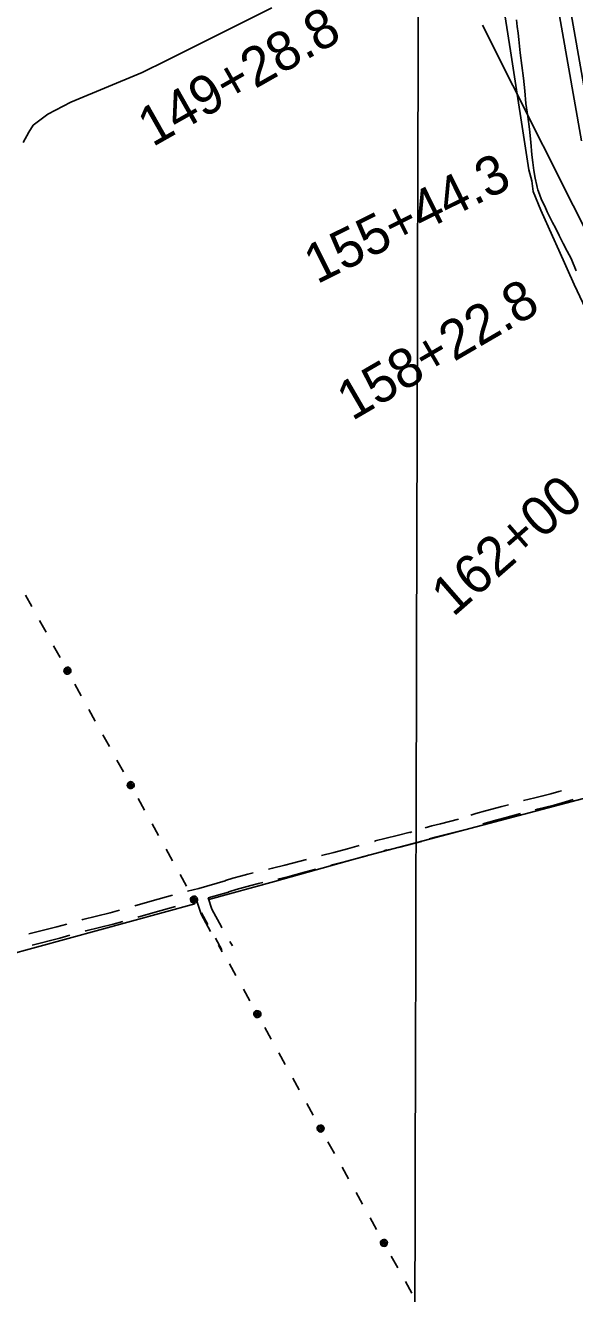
# Model space of a CAD drawing. Extents: x 3172231 to 3210228, y 940198 to 965780.
# Drawn here: x 3185930 to 3187335, y 947563 to 950801 of the extents above; entities that cross this region are included whole.
import ezdxf

# ---------------------------------------------------------------- set-up
doc = ezdxf.new("R2010")
doc.units = 0
for name, color, linetype in [('V-GRID-MAJR', 7, 'Continuous'), ('V-LEVE-TOET', 7, 'Continuous'), ('V-ROAD-CNTR', 7, 'Continuous'), ('V-SURV-IDEN', 7, 'Continuous'), ('V-SURV-LINE', 7, 'Continuous'), ('V-TOPO-BNDY', 7, 'Continuous'), ('V-TOPO-SHOR', 7, 'Continuous'), ('V-UTIL-LINE', 7, 'Continuous')]:
    doc.layers.add(name, color=color, linetype=linetype)

msp = doc.modelspace()

# ---------------------------------------------------------------- linework, layer by layer
at = {"layer": 'V-GRID-MAJR'}
msp.add_spline([(3186921.327, 945704.044), (3186937.193, 951764.175), (3186953.067, 957827.391), (3186968.941, 963890.658), (3186968.949, 963893.691)], degree=3, dxfattribs=at)
at = {"layer": 'V-LEVE-TOET'}
for points in [[(3187214.886, 950568.695), (3187210.038, 950601.33), (3187207.138, 950633.844), (3187203.677, 950666.309), (3187199.653, 950698.706), (3187195.065, 950731.028), (3187193.593, 950747.846), (3187191.915, 950764.648), (3187190.033, 950781.431), (3187187.948, 950798.192), (3187185.661, 950814.926)], [(3187338.839, 950174.429), (3187325.578, 950205.491), (3187315.129, 950224.93), (3187304.965, 950244.525), (3187295.09, 950264.266), (3187285.505, 950284.146), (3187278.327, 950297.732), (3187271.349, 950311.425), (3187264.572, 950325.217), (3187258, 950339.106), (3187253.571, 950348.457), (3187249.415, 950357.938), (3187245.538, 950367.534), (3187241.944, 950377.238), (3187240.508, 950380.76), (3187239.325, 950384.387), (3187238.403, 950388.09), (3187237.75, 950391.838), (3187234.067, 950411.356), (3187230.688, 950430.928), (3187227.614, 950450.552), (3187224.845, 950470.219), (3187222.293, 950503.114), (3187218.972, 950535.948), (3187214.886, 950568.695)]]:
    msp.add_lwpolyline(points, dxfattribs=at)
at = {"layer": 'V-ROAD-CNTR'}
for p, q in [((3186423.937, 948452.517), (3186433.604, 948435.73)), ((3186452.819, 948462.479), (3186459.602, 948450.7))]:
    msp.add_line(p, q, dxfattribs=at)
for points in [[(3187300.667, 948847.074), (3187294.429, 948845.194), (3187273.938, 948839.398), (3187253.351, 948833.949), (3187232.673, 948828.851), (3187203.831, 948822.231)], [(3187330.423, 948824.708), (3187302.841, 948816.396), (3187281.86, 948810.462), (3187260.781, 948804.883), (3187239.619, 948799.665), (3187233.987, 948798.372)], [(3187165.765, 948811.269), (3187148.235, 948806.428), (3187106.857, 948795.55), (3187106.857, 948795.452), (3187081.715, 948788.621), (3187069.347, 948785.032)], [(3187195.921, 948788.474), (3187156.043, 948777.462), (3187136.857, 948772.418), (3187136.857, 948772.516), (3187099.518, 948762.371)], [(3187038.129, 948774.293), (3186991.45, 948762.73), (3186969.775, 948756.959), (3186952.625, 948752.071)], [(3186918.47, 948741.684), (3186913.948, 948740.261), (3186913.948, 948740.876), (3186880.732, 948732.298), (3186824.881, 948718.88), (3186824.881, 948718.343), (3186822.612, 948717.688)], [(3187056.353, 948747.901), (3186998.916, 948733.672), (3186977.745, 948728.037), (3186963.995, 948724.117)], [(3186784.126, 948706.793), (3186754.118, 948698.701), (3186718.622, 948689.652), (3186718.622, 948689.634), (3186687.363, 948681.617)], [(3186942.865, 948717.359), (3186887.986, 948703.188), (3186854.881, 948695.234), (3186854.881, 948695.771), (3186846.487, 948693.351)], [(3186648.725, 948671.272), (3186613.758, 948661.714), (3186613.758, 948661.845), (3186593.652, 948656.586), (3186562.317, 948648.97), (3186551.992, 948646.628)], [(3186808.054, 948682.268), (3186803.034, 948680.82), (3186761.73, 948669.681), (3186748.622, 948666.34), (3186748.622, 948666.358), (3186711.376, 948656.805)], [(3186513.099, 948637.536), (3186499.566, 948634.131), (3186480.239, 948628.907), (3186461.009, 948623.345), (3186441.942, 948617.472), (3186440.791, 948617.107)], [(3186672.67, 948646.717), (3186643.758, 948638.814), (3186643.758, 948638.683), (3186600.992, 948627.496), (3186576.03, 948621.429)], [(3186441.151, 948617.216), (3186374.159, 948597.786), (3186344.888, 948590.212)], [(3186537.146, 948612.447), (3186526.048, 948609.859), (3186507.14, 948605.101), (3186488.321, 948600.015), (3186469.593, 948594.599), (3186450.896, 948588.84), (3186449.867, 948588.513)], [(3186306.212, 948580.012), (3186254.538, 948565.601), (3186209.934, 948553.005)], [(3186353.582, 948561.707), (3186368.441, 948565.319), (3186379.78, 948532.232), (3186404.043, 948487.218)], [(3186449.507, 948588.404), (3186397.42, 948573.296)], [(3186397.42, 948573.296), (3186407.36, 948544.294), (3186431.559, 948499.398), (3186432.858, 948497.142)], [(3186171.506, 948541.904), (3186147.614, 948534.956), (3186077.311, 948518.224), (3186074.57, 948517.456)], [(3186314.57, 948551.198), (3186262.644, 948536.717), (3186218.291, 948524.192)], [(3186036.056, 948506.653), (3186011.3, 948499.709), (3185939.194, 948481.836)], [(3186179.863, 948513.092), (3186155.28, 948505.942), (3186084.837, 948489.178), (3186082.927, 948488.642)], [(3186044.413, 948477.839), (3186018.962, 948470.701), (3185947.557, 948453.001)]]:
    msp.add_lwpolyline(points, dxfattribs=at)
at = {"layer": 'V-SURV-LINE'}
for points in [[(3187352.015, 950506.264), (3187252.517, 951073.281)], [(3187282.065, 951078.466), (3187381.563, 950511.449)]]:
    msp.add_lwpolyline(points, dxfattribs=at)
at = {"layer": 'V-TOPO-BNDY'}
msp.add_line((3188711.943, 947598.102), (3187098.67, 950801.485), dxfattribs=at)
at = {"layer": 'V-TOPO-SHOR'}
for points in [[(3187444.879, 949904.107), (3187333.109, 950139.787), (3187294.092, 950227.268), (3187278.13, 950262.975), (3187247.976, 950329.034), (3187228.478, 950377.233), (3187224.978, 950403.992), (3187217.915, 950432.543), (3187170.514, 950735.832), (3187137.155, 950948.134), (3187124.844, 951017.716), (3187105.302, 951048.081), (3187096.429, 951065.937), (3187091.123, 951083.784), (3187084.021, 951096.285), (3187076.931, 951114.136), (3187069.837, 951130.204), (3187057.394, 951146.285), (3187039.613, 951167.729), (3187014.73, 951201.674), (3186904.603, 951380.283), (3186833.52, 951482.11), (3186572.347, 951878.662)], [(3185925.148, 950501.724), (3185939.481, 950528.439), (3185950.226, 950546.246), (3185987.747, 950574.687), (3186046.672, 950604.858), (3186228.764, 950681.093), (3186291.256, 950711.255), (3186560.877, 950846.124)], [(3187812.56, 948947.316), (3186795.38, 948678.76), (3186566.952, 948615.123), (3186399.203, 948569.171)], [(3186363.509, 948558.559), (3185796.016, 948403.026), (3185446.241, 948307.59)]]:
    msp.add_lwpolyline(points, dxfattribs=at)
at = {"layer": 'V-UTIL-LINE'}
for points in [[(3185930.822, 949346.689), (3185947.311, 949316.955)], [(3185966.709, 949281.974), (3185983.197, 949252.24)], [(3186002.595, 949217.258), (3186019.084, 949187.524)], [(3186037.996, 949153.418), (3186039.272, 949155.997), (3186036.972, 949155.645), (3186035.817, 949153.154), (3186037.512, 949150.766), (3186040.558, 949152.271), (3186041.959, 949156.745), (3186038.523, 949159.275), (3186033.796, 949158.133), (3186032.316, 949153.8), (3186033.584, 949149.513), (3186038.074, 949147.75), (3186043.038, 949150.133), (3186045.867, 949157.782), (3186043.598, 949160.462), (3186040.476, 949162.069), (3186036.976, 949162.36), (3186033.632, 949161.288), (3186030.952, 949159.019), (3186029.344, 949155.897), (3186029.054, 949152.397), (3186030.125, 949149.053), (3186032.395, 949146.373), (3186035.517, 949144.766), (3186039.017, 949144.476), (3186042.361, 949145.547), (3186045.041, 949147.816), (3186046.648, 949150.938), (3186046.938, 949154.438), (3186045.867, 949157.782)], [(3186056.911, 949119.31), (3186073.399, 949089.576)], [(3186092.797, 949054.594), (3186109.286, 949024.86)], [(3186128.684, 948989.879), (3186145.172, 948960.145)], [(3186164.558, 948925.157), (3186181.02, 948895.408)], [(3186199.903, 948861.285), (3186201.181, 948863.863), (3186198.881, 948863.513), (3186197.724, 948861.023), (3186199.416, 948858.634), (3186202.464, 948860.136), (3186203.869, 948864.609), (3186200.435, 948867.142), (3186195.707, 948866.004), (3186194.224, 948861.672), (3186195.488, 948857.384), (3186199.977, 948855.618), (3186204.942, 948857.996), (3186207.778, 948865.643), (3186205.511, 948868.324), (3186202.39, 948869.935), (3186198.891, 948870.228), (3186195.546, 948869.16), (3186192.864, 948866.893), (3186191.254, 948863.772), (3186190.961, 948860.272), (3186192.029, 948856.927), (3186194.296, 948854.246), (3186197.417, 948852.635), (3186200.916, 948852.342), (3186204.261, 948853.41), (3186206.943, 948855.677), (3186208.553, 948858.798), (3186208.846, 948862.298), (3186207.778, 948865.643)], [(3186218.787, 948827.161), (3186235.249, 948797.412)], [(3186254.617, 948762.413), (3186271.079, 948732.664)], [(3186290.446, 948697.666), (3186306.908, 948667.917)], [(3186326.276, 948632.919), (3186342.738, 948603.17)], [(3186361.622, 948569.048), (3186362.9, 948571.626), (3186360.599, 948571.277), (3186359.443, 948568.786), (3186361.135, 948566.397), (3186364.183, 948567.899), (3186365.588, 948572.372), (3186362.154, 948574.905), (3186357.425, 948573.767), (3186355.942, 948569.436), (3186357.207, 948565.148), (3186361.695, 948563.381), (3186366.66, 948565.759), (3186369.497, 948573.406), (3186367.23, 948576.088), (3186364.109, 948577.698), (3186360.609, 948577.991), (3186357.264, 948576.923), (3186354.583, 948574.656), (3186352.973, 948571.535), (3186352.679, 948568.036), (3186353.747, 948564.69), (3186356.014, 948562.009), (3186359.135, 948560.399), (3186362.635, 948560.105), (3186365.98, 948561.174), (3186368.662, 948563.44), (3186370.272, 948566.561), (3186370.565, 948570.061), (3186369.497, 948573.406)], [(3186380.505, 948534.923), (3186396.968, 948505.174)], [(3186416.336, 948470.176), (3186432.798, 948440.427)], [(3186452.165, 948405.429), (3186468.628, 948375.68)], [(3186487.996, 948340.682), (3186504.458, 948310.933)], [(3186523.341, 948276.811), (3186524.618, 948279.389), (3186522.318, 948279.04), (3186521.161, 948276.549), (3186522.854, 948274.16), (3186525.901, 948275.662), (3186527.306, 948280.135), (3186523.873, 948282.668), (3186519.144, 948281.53), (3186517.661, 948277.199), (3186518.925, 948272.911), (3186523.414, 948271.144), (3186528.379, 948273.523), (3186531.216, 948281.169), (3186528.949, 948283.851), (3186525.828, 948285.461), (3186522.328, 948285.754), (3186518.983, 948284.686), (3186516.301, 948282.419), (3186514.691, 948279.298), (3186514.398, 948275.799), (3186515.466, 948272.454), (3186517.733, 948269.772), (3186520.854, 948268.162), (3186524.354, 948267.868), (3186527.699, 948268.937), (3186530.38, 948271.204), (3186531.991, 948274.324), (3186532.284, 948277.824), (3186531.216, 948281.169)], [(3186542.225, 948242.686), (3186558.687, 948212.937)], [(3186578.055, 948177.939), (3186594.517, 948148.19)], [(3186613.884, 948113.192), (3186630.347, 948083.443)], [(3186649.725, 948048.45), (3186666.21, 948018.714)], [(3186685.117, 947984.606), (3186686.393, 947987.185), (3186684.093, 947986.834), (3186682.938, 947984.343), (3186684.632, 947981.955), (3186687.678, 947983.459), (3186689.08, 947987.933), (3186685.644, 947990.463), (3186680.917, 947989.322), (3186679.437, 947984.989), (3186680.705, 947980.702), (3186685.194, 947978.939), (3186690.158, 947981.321), (3186692.988, 947988.97), (3186690.72, 947991.65), (3186687.597, 947993.258), (3186684.098, 947993.548), (3186680.753, 947992.478), (3186678.073, 947990.209), (3186676.466, 947987.087), (3186676.175, 947983.587), (3186677.246, 947980.243), (3186679.515, 947977.563), (3186682.637, 947975.955), (3186686.136, 947975.664), (3186689.481, 947976.735), (3186692.161, 947979.004), (3186693.769, 947982.126), (3186694.059, 947985.626), (3186692.988, 947988.97)], [(3186704.028, 947950.495), (3186720.513, 947920.759)], [(3186739.907, 947885.775), (3186756.392, 947856.039)], [(3186775.785, 947821.056), (3186792.27, 947791.32)], [(3186811.664, 947756.336), (3186828.149, 947726.6)], [(3186847.055, 947692.491), (3186848.33, 947695.069), (3186846.03, 947694.718), (3186844.875, 947692.227), (3186846.569, 947689.839), (3186849.616, 947691.344), (3186851.018, 947695.817), (3186847.582, 947698.348), (3186842.854, 947697.207), (3186841.375, 947692.874), (3186842.642, 947688.587), (3186847.132, 947686.823), (3186852.095, 947689.206), (3186854.926, 947696.854), (3186852.657, 947699.534), (3186849.535, 947701.142), (3186846.035, 947701.433), (3186842.691, 947700.362), (3186840.011, 947698.093), (3186838.403, 947694.971), (3186838.112, 947691.471), (3186839.183, 947688.127), (3186841.452, 947685.447), (3186844.574, 947683.839), (3186848.074, 947683.549), (3186851.418, 947684.619), (3186854.098, 947686.888), (3186855.706, 947690.01), (3186855.997, 947693.51), (3186854.926, 947696.854)], [(3186865.967, 947658.381), (3186882.452, 947628.644)], [(3186901.846, 947593.66), (3186918.331, 947563.923)]]:
    msp.add_lwpolyline(points, dxfattribs=at)

# ---------------------------------------------------------------- texts
at = {"layer": 'V-SURV-IDEN'}
for s, rotation, p in [('149+28.8', 29.559759, (3186255.535, 950489.457)), ('155+44.3', 26.476506, (3186675.955, 950139.528)), ('158+22.8', 30.166849, (3186765.709, 949790.175)), ('162+00.4', 41.207936, (3187023.739, 949288.824))]:
    msp.add_text(s, height=100, rotation=rotation, dxfattribs=at).set_placement(p)

doc.saveas('drawing.dxf')
